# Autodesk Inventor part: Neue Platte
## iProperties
Created: 2006-10
Part Number: Neue Platte
Cost Center: 0,612 kg
Material: Stahl (schweißbar)
Document SubType Name: Modeling
Designer: Schmidt
Authority: 77800 mm^3
Density: 7.86 g/cm^3
SaveDate: 2006-10-28
SaveTime: 21:07
TotalMass: 0,612 kg
TotalVolume: 77800 mm^3
Author: Schmidt
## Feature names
1. Extrusion2
2. Bohrung2 [Hole]
